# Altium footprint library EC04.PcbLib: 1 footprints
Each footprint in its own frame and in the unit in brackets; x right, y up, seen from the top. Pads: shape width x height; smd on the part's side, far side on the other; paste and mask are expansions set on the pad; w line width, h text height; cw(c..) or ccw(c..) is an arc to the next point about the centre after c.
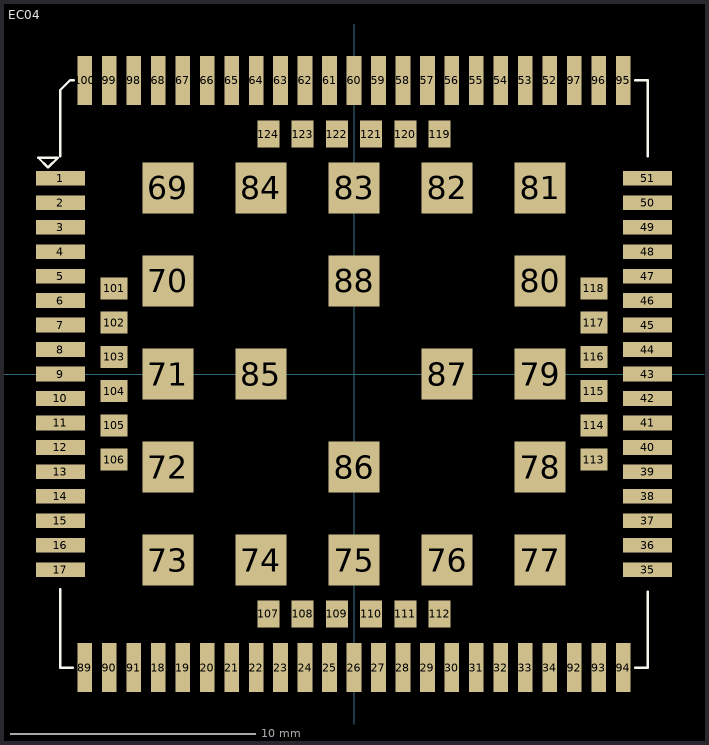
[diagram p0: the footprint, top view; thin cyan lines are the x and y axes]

## EC04 [mm]
pads (124):
  rect 2x0.6 smd paste-0.05 mask+0.025: 1(-12,8) 2(-12,7) 3(-12,6) 4(-12,5) 5(-12,4) 6(-12,3) 7(-12,2) 8(-12,1) 9(-12,0) 10(-12,-1) 11(-12,-2) 12(-12,-3) 13(-12,-4) 14(-12,-5) 15(-12,-6) 16(-12,-7) 17(-12,-8) 35(12,-8) 36(12,-7) 37(12,-6) 38(12,-5) 39(12,-4) 40(12,-3) 41(12,-2) 42(12,-1) 43(12,0) 44(12,1) 45(12,2) 46(12,3) 47(12,4) 48(12,5) 49(12,6) 50(12,7) 51(12,8)
  rect 0.6x2 smd paste-0.05 mask+0.025: 18(-8,-12) 19(-7,-12) 20(-6,-12) 21(-5,-12) 22(-4,-12) 23(-3,-12) 24(-2,-12) 25(-1,-12) 26(0,-12) 27(1,-12) 28(2,-12) 29(3,-12) 30(4,-12) 31(5,-12) 32(6,-12) 33(7,-12) 34(8,-12) 52(8,12) 53(7,12) 54(6,12) 55(5,12) 56(4,12) 57(3,12) 58(2,12) 59(1,12) 60(0,12) 61(-1,12) 62(-2,12) 63(-3,12) 64(-4,12) 65(-5,12) 66(-6,12) 67(-7,12) 68(-8,12) 89(-11,-12) 90(-10,-12) 91(-9,-12) 92(9,-12) 93(10,-12) 94(11,-12) 95(11,12) 96(10,12) 97(9,12) 98(-9,12) 99(-10,12) 100(-11,12)
  rect 2.1x2.1 smd mask+0.025: 69(-7.6,7.6) 70(-7.6,3.8) 71(-7.6,0) 72(-7.6,-3.8) 73(-7.6,-7.6) 74(-3.8,-7.6) 75(0,-7.6) 76(3.8,-7.6) 77(7.6,-7.6) 78(7.6,-3.8) 79(7.6,0) 80(7.6,3.8) 81(7.6,7.6) 82(3.8,7.6) 83(0,7.6) 84(-3.8,7.6) 85(-3.8,0) 86(0,-3.8) 87(3.8,0) 88(0,3.8)
  rect 1.1x0.9 smd mask+0.03: 101(-9.8,3.5) 102(-9.8,2.1) 103(-9.8,0.7) 104(-9.8,-0.7) 105(-9.8,-2.1) 106(-9.8,-3.5) 113(9.8,-3.5) 114(9.8,-2.1) 115(9.8,-0.7) 116(9.8,0.7) 117(9.8,2.1) 118(9.8,3.5)
  rect 0.9x1.1 smd mask+0.03: 107(-3.5,-9.8) 108(-2.1,-9.8) 109(-0.7,-9.8) 110(0.7,-9.8) 111(2.1,-9.8) 112(3.5,-9.8) 119(3.5,9.8) 120(2.1,9.8) 121(0.7,9.8) 122(-0.7,9.8) 123(-2.1,9.8) 124(-3.5,9.8)
Top Overlay:
  lines w0.1: -12,-8.8 -12,-12 -11.5,-12 ; -12,8.9 -12,11.6 -11.6,12 -11.45,12 ; 11.5,-12 12,-12 12,-8.9 ; 11.5,12 12,12 12,8.9 ; -12.9,8.836 -12.1,8.836 -12.5,8.436 -12.9,8.836
Top Paste:
  drawing of 80 lines, arcs and shapes, not listed
3D body "A7670C-R2模块.STEP": height 2.4, standoff -0.01, extent -12.01,-12.01 12.01,12.01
